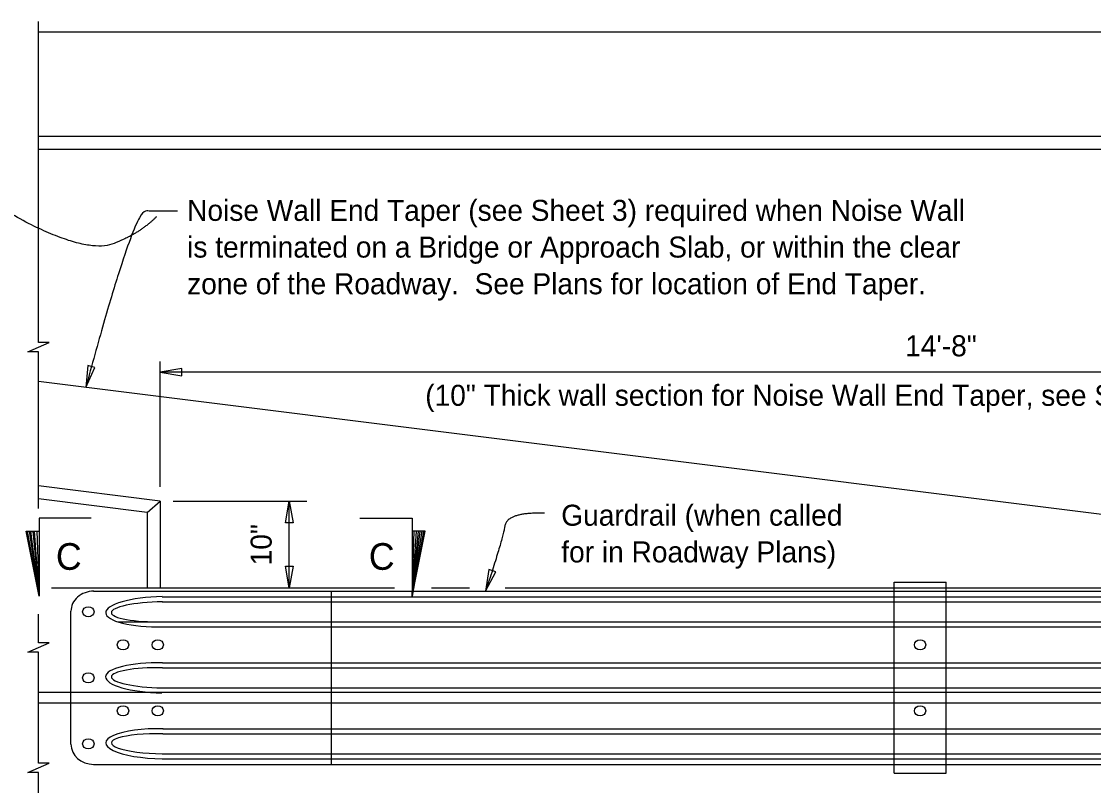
# Model space of a CAD drawing. Extents: x 120631.6 to 120706.2, y 120663.5 to 120716.4.
# Drawn here: x 120654.13 to 120664.42, y 120695.32 to 120702.65 of the extents above; entities that cross this region are included whole.
import ezdxf

# ---------------------------------------------------------------- set-up
doc = ezdxf.new("R2010")
doc.units = 0
for name, color, linetype in [('Dimension', 7, 'Continuous'), ('SteelMisc_h', 7, 'Continuous'), ('TextStructures', 7, 'Continuous'), ('TrafBarrierConc', 7, 'Continuous')]:
    doc.layers.add(name, color=color, linetype=linetype)

msp = doc.modelspace()

# ---------------------------------------------------------------- linework, layer by layer
at = {"layer": 'Dimension'}
for p, q in [((120655.461, 120698.181), (120655.461, 120699.383)), ((120670.127, 120699.283), (120655.461, 120699.283)), ((120655.587, 120698.046), (120656.87, 120698.046)), ((120656.701, 120697.213), (120656.701, 120698.046)), ((120654.301, 120697.133), (120654.191, 120697.758)), ((120654.205, 120697.758), (120654.301, 120697.133)), ((120654.301, 120697.133), (120654.221, 120697.758)), ((120654.24, 120697.758), (120654.301, 120697.133)), ((120654.301, 120697.133), (120654.258, 120697.758)), ((120654.278, 120697.758), (120654.301, 120697.133)), ((120657.879, 120697.133), (120657.975, 120697.76)), ((120657.879, 120697.133), (120657.9, 120697.76)), ((120657.879, 120697.133), (120657.92, 120697.758)), ((120657.989, 120697.757), (120657.879, 120697.133)), ((120657.879, 120697.133), (120657.957, 120697.757)), ((120657.879, 120697.133), (120657.939, 120697.757))]:
    msp.add_line(p, q, dxfattribs=at)
for points in [[(120654.296, 120697.974), (120654.296, 120699.476), (120654.193, 120699.476), (120654.296, 120699.521), (120654.399, 120699.566), (120654.296, 120699.566), (120654.296, 120702.646)], [(120654.801, 120697.883), (120654.301, 120697.883), (120654.301, 120697.133), (120654.176, 120697.758), (120654.301, 120697.758)], [(120657.377, 120697.883), (120657.879, 120697.883), (120657.879, 120697.133), (120658.004, 120697.758), (120657.879, 120697.758)], [(120654.296, 120696.213), (120654.296, 120696.597), (120654.193, 120696.597), (120654.296, 120696.642), (120654.399, 120696.687), (120654.296, 120696.687), (120654.296, 120696.96)], [(120654.296, 120693.321), (120654.296, 120695.442), (120654.193, 120695.442), (120654.296, 120695.487), (120654.399, 120695.532), (120654.296, 120695.532), (120654.296, 120696.213)]]:
    msp.add_lwpolyline(points, dxfattribs=at)
for points in [[(120654.748, 120699.135), (120654.837, 120699.327), (120654.769, 120699.345)], [(120655.461, 120699.283), (120655.669, 120699.247), (120655.669, 120699.318)], [(120656.701, 120698.046), (120656.737, 120697.838), (120656.666, 120697.838)], [(120656.701, 120697.213), (120656.666, 120697.421), (120656.737, 120697.421)], [(120658.584, 120697.18), (120658.683, 120697.367), (120658.616, 120697.389)]]:
    msp.add_lwpolyline(points, close=True, dxfattribs=at)
for points in [[(120655.427, 120700.773), (120655.261, 120700.607), (120654.761, 120700.419), (120653.547, 120701.045), (120653.121, 120701.803)], [(120655.627, 120700.826), (120655.431, 120700.826), (120655.207, 120700.826), (120654.748, 120699.135)], [(120659.15, 120697.929), (120658.791, 120697.94), (120658.746, 120697.672), (120658.584, 120697.18)]]:
    msp.add_open_spline(points, degree=2, dxfattribs=at)
at = {"layer": 'SteelMisc_h'}
for p, q in [((120662.502, 120695.434), (120662.502, 120697.267)), ((120662.502, 120697.267), (120663.001, 120697.267)), ((120663.002, 120695.434), (120663.001, 120697.267)), ((120654.824, 120697.181), (120674.539, 120697.181)), ((120655.482, 120697.128), (120674.539, 120697.128)), ((120657.106, 120695.52), (120657.106, 120697.181)), ((120655.483, 120697.08), (120674.539, 120697.08)), ((120654.606, 120695.713), (120654.606, 120696.988)), ((120655.058, 120696.887), (120674.539, 120696.887)), ((120655.489, 120696.839), (120674.539, 120696.839)), ((120655.486, 120696.495), (120674.539, 120696.495)), ((120655.484, 120696.447), (120674.539, 120696.447)), ((120655.479, 120696.254), (120674.539, 120696.254)), ((120655.488, 120695.814), (120674.539, 120695.814)), ((120655.489, 120695.862), (120674.539, 120695.862)), ((120655.482, 120695.621), (120674.539, 120695.621)), ((120655.483, 120695.573), (120674.539, 120695.573)), ((120654.824, 120695.52), (120674.539, 120695.52)), ((120662.502, 120695.434), (120663.002, 120695.434))]:
    msp.add_line(p, q, dxfattribs=at)
for centre, major_axis, ratio, start_param, end_param in [((120654.825, 120696.988), (0.219, 0), 0.882613, 1.570796, 3.141593), ((120655.486, 120696.984), (-0.546, -0.01), 0.264749, 4.713933, 7.855525), ((120655.486, 120696.984), (-0.492, -0.009), 0.196063, 4.713495, 7.855087), ((120655.482, 120696.35), (-0.543, 0.01), 0.266477, 4.71081, 7.852402), ((120655.482, 120696.35), (-0.488, 0.009), 0.197486, 4.711258, 7.85285), ((120655.486, 120695.717), (-0.546, 0.01), 0.264749, 4.710845, 7.852438), ((120655.486, 120695.717), (-0.492, 0.009), 0.196063, 4.711283, 7.852876), ((120654.825, 120695.713), (0.219, 0), 0.882613, 3.141593, 4.712389)]:
    msp.add_ellipse(centre, major_axis=major_axis, ratio=ratio, start_param=start_param, end_param=end_param, dxfattribs=at)
for centre in [(120654.773, 120696.984), (120655.106, 120696.667), (120655.439, 120696.667), (120662.752, 120696.667), (120654.773, 120696.35), (120655.106, 120696.034), (120655.439, 120696.034), (120662.752, 120696.034), (120654.773, 120695.717)]:
    msp.add_ellipse(centre, major_axis=(0.0547, 0), ratio=0.882613, dxfattribs=at)
at = {"layer": 'TrafBarrierConc'}
for p, q in [((120654.296, 120702.546), (120670.065, 120702.546)), ((120654.296, 120701.546), (120670.127, 120701.546)), ((120654.296, 120701.421), (120670.127, 120701.421)), ((120670.127, 120697.213), (120654.296, 120699.192)), ((120655.461, 120698.046), (120654.296, 120698.192)), ((120655.336, 120697.937), (120654.296, 120698.067)), ((120655.336, 120697.937), (120655.461, 120698.046)), ((120655.461, 120698.046), (120655.461, 120697.213)), ((120655.336, 120697.937), (120655.336, 120697.213)), ((120654.421, 120697.213), (120657.711, 120697.213)), ((120658.066, 120697.213), (120658.431, 120697.213)), ((120658.773, 120697.213), (120670.127, 120697.213)), ((120654.296, 120696.213), (120670.127, 120696.213)), ((120654.296, 120696.109), (120670.127, 120696.109))]:
    msp.add_line(p, q, dxfattribs=at)

# ---------------------------------------------------------------- texts
at = {"layer": 'Dimension'}
for s, p in [('Noise Wall End Taper (see Sheet 3) required when Noise Wall ', (120655.721, 120700.733)), ('is terminated on a Bridge or Approach Slab, or within the clear ', (120655.721, 120700.381)), ('zone of the Roadway.  See Plans for location of End Taper.', (120655.721, 120700.029)), ('Guardrail (when called ', (120659.31, 120697.809)), ('for in Roadway Plans)', (120659.31, 120697.457))]:
    msp.add_text(s, height=0.2016, dxfattribs=at).set_placement(p)
at = {"layer": 'TextStructures'}
for s, height, p in [('14\'-8" ', 0.2016, (120662.609, 120699.434)), ('(10" Thick wall section for Noise Wall End Taper, see Section C-C)', 0.2016, (120658.005, 120698.959)), ('C', 0.256, (120654.462, 120697.386)), ('C', 0.256, (120657.464, 120697.386))]:
    msp.add_text(s, height=height, dxfattribs=at).set_placement(p)
msp.add_text('10"', height=0.2016, rotation=90, dxfattribs=at).set_placement((120656.532, 120697.429))

doc.saveas('drawing.dxf')
